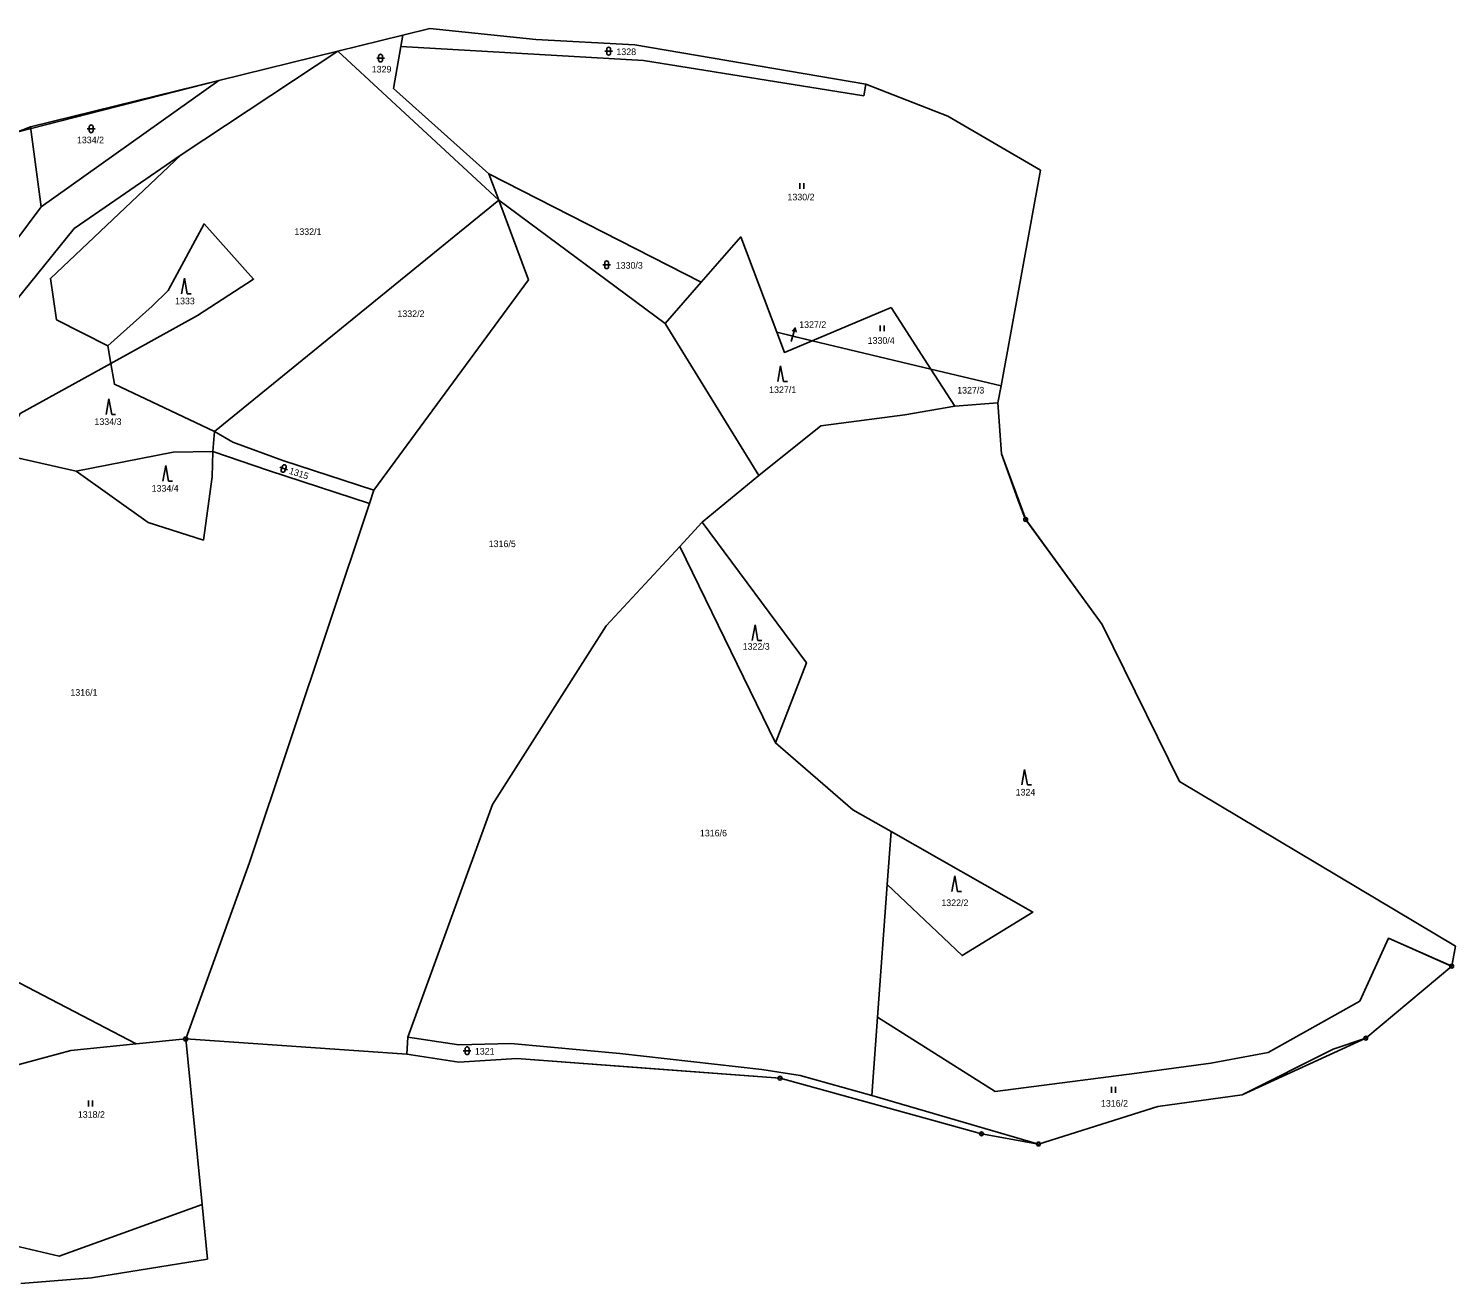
# Model space of a CAD drawing. Extents: x -760642 to -757221, y -1092371 to -1088855.
# Drawn here: x -758208 to -757841.3, y -1091740.5 to -1091418.1 of the extents above; entities that cross this region are included whole.
import ezdxf

# ---------------------------------------------------------------- set-up
doc = ezdxf.new("R2010")
doc.units = 0
for name, color, linetype in [('Vrstva 1', 7, 'Continuous'), ('Vrstva 13', 7, 'Continuous'), ('Vrstva 16', 7, 'Continuous'), ('Vrstva 18', 7, 'Continuous'), ('Vrstva 24', 7, 'Continuous'), ('Vrstva 25', 7, 'Continuous'), ('Vrstva 28', 7, 'Continuous'), ('Vrstva 30', 7, 'Continuous')]:
    doc.layers.add(name, color=color, linetype=linetype)

msp = doc.modelspace()

# ---------------------------------------------------------------- linework, layer by layer
at = {"layer": 'Vrstva 1'}
for p, q in [((-758112.36, -1091422.75), (-758111.85, -1091419.86)), ((-758168.83, -1091450.63), (-758128.51, -1091423.96)), ((-758128.51, -1091423.96), (-758087.19, -1091462.22)), ((-758114.26, -1091433.58), (-758112.36, -1091422.75)), ((-758112.36, -1091422.75), (-758049.99, -1091426.37)), ((-758049.99, -1091426.37), (-757993.39, -1091435.44)), ((-758204.82, -1091463.99), (-758159.15, -1091431.49)), ((-757993.39, -1091435.44), (-757992.81, -1091432.47)), ((-758114.26, -1091433.58), (-758089.71, -1091455.48)), ((-758207.52, -1091443.37), (-758204.82, -1091463.99)), ((-758202.42, -1091482.36), (-758168.83, -1091450.63)), ((-758196.3, -1091469.53), (-758168.83, -1091450.63)), ((-758089.71, -1091455.48), (-758035.17, -1091483.32)), ((-758089.71, -1091455.48), (-758087.19, -1091462.22)), ((-758087.19, -1091462.22), (-758160.27, -1091521.64)), ((-758087.19, -1091462.22), (-758044.43, -1091493.9)), ((-758087.19, -1091462.22), (-758079.54, -1091482.73)), ((-758211.58, -1091473.01), (-758204.82, -1091463.99)), ((-758196.3, -1091469.53), (-758215.33, -1091493.07)), ((-758172.17, -1091485.42), (-758162.91, -1091468.32)), ((-758162.91, -1091468.32), (-758150.19, -1091482.53)), ((-758024.99, -1091471.68), (-758035.17, -1091483.32)), ((-758015.74, -1091496.19), (-758024.99, -1091471.68)), ((-758202.42, -1091482.36), (-758200.82, -1091492.96)), ((-758164.59, -1091491.89), (-758150.19, -1091482.53)), ((-758079.54, -1091482.73), (-758119.27, -1091536.7)), ((-758035.17, -1091483.32), (-758044.43, -1091493.9)), ((-758176.26, -1091489.43), (-758172.17, -1091485.42)), ((-758187.63, -1091499.68), (-758176.26, -1091489.43)), ((-758186.87, -1091504.19), (-758164.59, -1091491.89)), ((-758006.66, -1091498.35), (-757986.38, -1091489.82)), ((-757986.38, -1091489.82), (-757976.11, -1091505.63)), ((-758200.82, -1091492.96), (-758187.63, -1091499.68)), ((-758044.43, -1091493.9), (-758020.39, -1091532.94)), ((-758015.74, -1091496.19), (-758006.66, -1091498.35)), ((-758015.74, -1091496.19), (-758013.79, -1091501.35)), ((-758013.79, -1091501.35), (-758006.66, -1091498.35)), ((-758006.66, -1091498.35), (-757976.11, -1091505.63)), ((-758186.87, -1091504.19), (-758187.63, -1091499.68)), ((-758210.23, -1091517.07), (-758186.87, -1091504.19)), ((-758185.98, -1091509.54), (-758186.87, -1091504.19)), ((-757976.11, -1091505.63), (-757969.99, -1091515.16)), ((-757976.11, -1091505.63), (-757958.1, -1091509.92)), ((-758185.98, -1091509.54), (-758160.27, -1091521.64)), ((-758004.45, -1091520.17), (-757982.84, -1091517.41)), ((-757982.84, -1091517.41), (-757969.99, -1091515.16)), ((-757969.99, -1091515.16), (-757958.91, -1091514.31)), ((-758004.45, -1091520.17), (-758020.39, -1091532.94)), ((-758160.27, -1091521.64), (-758160.66, -1091526.8)), ((-758160.27, -1091521.64), (-758155.56, -1091524.44)), ((-758155.56, -1091524.44), (-758142.67, -1091529.12)), ((-758215.93, -1091527.36), (-758195.84, -1091531.84)), ((-758170.85, -1091526.94), (-758195.84, -1091531.84)), ((-758170.85, -1091526.94), (-758160.66, -1091526.8)), ((-758160.66, -1091526.8), (-758160.85, -1091533.31)), ((-758160.66, -1091526.8), (-758146.35, -1091531.71)), ((-758177.34, -1091545.07), (-758195.84, -1091531.84)), ((-758146.35, -1091531.71), (-758120.38, -1091540.17)), ((-758142.67, -1091529.12), (-758119.27, -1091536.7)), ((-758160.85, -1091533.31), (-758163.08, -1091549.56)), ((-758020.39, -1091532.94), (-758034.93, -1091544.97)), ((-758120.38, -1091540.17), (-758119.27, -1091536.7)), ((-758120.38, -1091540.17), (-758151.24, -1091632.36)), ((-758177.34, -1091545.07), (-758163.08, -1091549.56)), ((-758034.93, -1091544.97), (-758040.69, -1091551.19)), ((-758034.93, -1091544.97), (-758008.13, -1091581.07)), ((-758040.69, -1091551.19), (-758059.6, -1091571.6)), ((-758016.08, -1091601.69), (-758040.69, -1091551.19)), ((-758059.6, -1091571.6), (-758088.81, -1091617.52)), ((-758008.13, -1091581.07), (-758016.08, -1091601.69)), ((-758016.08, -1091601.69), (-757996.2, -1091618.83)), ((-758088.81, -1091617.52), (-758110.52, -1091677.3)), ((-757996.2, -1091618.83), (-757986.31, -1091624.44)), ((-757986.31, -1091624.44), (-757987.33, -1091638.06)), ((-757986.31, -1091624.44), (-757949.89, -1091645.11)), ((-758151.24, -1091632.36), (-758167.65, -1091677.73)), ((-757987.33, -1091638.06), (-757989.87, -1091672.08)), ((-757968.11, -1091656.3), (-757987.33, -1091638.06)), ((-758246.49, -1091644.53), (-758180.41, -1091679.01)), ((-757949.89, -1091645.11), (-757968.11, -1091656.3)), ((-757865.85, -1091668), (-757858.55, -1091651.84)), ((-757858.55, -1091651.84), (-757842.28, -1091659.03)), ((-757889.42, -1091681.16), (-757865.85, -1091668)), ((-757989.87, -1091672.08), (-757991.33, -1091692.26)), ((-757989.87, -1091672.08), (-757959.6, -1091691.26)), ((-758167.65, -1091677.73), (-758180.41, -1091679.01)), ((-758110.52, -1091677.3), (-758110.78, -1091681.67)), ((-758110.52, -1091677.3), (-758097.42, -1091679.19)), ((-758097.42, -1091679.19), (-758084.11, -1091678.93)), ((-758084.11, -1091678.93), (-758056.08, -1091681.47)), ((-758197.14, -1091680.68), (-758234.93, -1091690.88)), ((-758180.41, -1091679.01), (-758197.14, -1091680.68)), ((-758056.08, -1091681.47), (-758019.55, -1091685.55)), ((-757904.14, -1091683.97), (-757889.42, -1091681.16)), ((-758019.55, -1091685.55), (-758009.76, -1091687.13)), ((-757923.24, -1091686.53), (-757904.14, -1091683.97)), ((-758009.76, -1091687.13), (-757991.33, -1091692.26)), ((-757959.6, -1091691.26), (-757923.24, -1091686.53)), ((-757991.33, -1091692.26), (-757948.47, -1091704.71)), ((-758200.18, -1091733.5), (-758163.46, -1091720.21)), ((-758221.61, -1091728.5), (-758200.18, -1091733.5))]:
    msp.add_line(p, q, dxfattribs=at)
at = {"layer": 'Vrstva 13'}
for p, q in [((-758111.85, -1091419.86), (-758104.89, -1091418.15)), ((-758104.89, -1091418.15), (-758077.63, -1091420.92)), ((-758128.51, -1091423.96), (-758111.85, -1091419.86)), ((-758077.63, -1091420.92), (-758052.21, -1091422.34)), ((-758159.15, -1091431.49), (-758128.51, -1091423.96)), ((-758052.21, -1091422.34), (-757992.81, -1091432.47)), ((-758207.52, -1091443.37), (-758159.15, -1091431.49)), ((-757992.81, -1091432.47), (-757971.76, -1091440.66)), ((-758207.52, -1091443.37), (-758211.02, -1091444.76)), ((-757971.76, -1091440.66), (-757947.92, -1091454.57)), ((-757958.1, -1091509.92), (-757947.92, -1091454.57)), ((-757958.91, -1091514.31), (-757958.1, -1091509.92)), ((-757958.91, -1091514.31), (-757958.02, -1091527.39)), ((-757958.02, -1091527.39), (-757953.68, -1091539.42)), ((-757953.68, -1091539.42), (-757951.77, -1091544.28)), ((-757951.77, -1091544.28), (-757932.12, -1091571.24)), ((-757932.12, -1091571.24), (-757912.21, -1091611.59)), ((-757912.21, -1091611.59), (-757841.31, -1091653.87)), ((-757841.31, -1091653.87), (-757842.28, -1091659.03)), ((-757842.28, -1091659.03), (-757864.35, -1091677.52)), ((-758163.46, -1091720.21), (-758167.65, -1091677.73)), ((-758110.78, -1091681.67), (-758167.65, -1091677.73)), ((-757864.35, -1091677.52), (-757872.73, -1091680.38)), ((-758097.45, -1091683.71), (-758110.78, -1091681.67)), ((-757872.73, -1091680.38), (-757896.17, -1091692.09)), ((-758082.57, -1091682.71), (-758097.45, -1091683.71)), ((-758046.15, -1091685.44), (-758082.57, -1091682.71)), ((-758014.9, -1091687.79), (-758046.15, -1091685.44)), ((-757975.44, -1091698.69), (-758014.9, -1091687.79)), ((-757896.17, -1091692.09), (-757917.77, -1091695.05)), ((-757917.77, -1091695.05), (-757948.47, -1091704.71)), ((-757963.11, -1091702.09), (-757975.44, -1091698.69)), ((-757948.47, -1091704.71), (-757963.11, -1091702.09)), ((-758162.07, -1091734.29), (-758163.46, -1091720.21)), ((-758162.07, -1091734.29), (-758191.83, -1091739.12)), ((-758191.83, -1091739.12), (-758210.04, -1091740.53))]:
    msp.add_line(p, q, dxfattribs=at)
at = {"layer": 'Vrstva 16'}
for p, q in [((-758011.84, -1091497.93), (-758010.974, -1091495.058)), ((-758012.01, -1091498.51), (-758011.84, -1091497.93))]:
    msp.add_line(p, q, dxfattribs=at)
msp.add_lwpolyline([(-758011.741, -1091495.871), (-758010.974, -1091495.058), (-758010.784, -1091496.159)], dxfattribs=at)
at = {"layer": 'Vrstva 24'}
for centre, radius in [((-757951.77, -1091544.28), 0.5), ((-757951.77, -1091544.28), 0.0327), ((-757842.28, -1091659.03), 0.5), ((-757842.28, -1091659.03), 0.0327), ((-758167.65, -1091677.73), 0.5), ((-758167.65, -1091677.73), 0.0327), ((-757864.35, -1091677.52), 0.5), ((-757864.35, -1091677.52), 0.0327), ((-758014.9, -1091687.79), 0.5), ((-758014.9, -1091687.79), 0.0327), ((-757963.11, -1091702.09), 0.5), ((-757963.11, -1091702.09), 0.0327), ((-757948.47, -1091704.71), 0.5), ((-757948.47, -1091704.71), 0.0327)]:
    msp.add_circle(centre, radius, dxfattribs=at)
at = {"layer": 'Vrstva 25'}
for p, q in [((-758118.57, -1091425.74), (-758116.57, -1091425.74)), ((-758118.07, -1091426.24), (-758118.07, -1091425.24)), ((-758117.07, -1091426.24), (-758117.07, -1091425.24)), ((-758059.95, -1091423.97), (-758057.95, -1091423.97)), ((-758059.45, -1091424.47), (-758059.45, -1091423.47)), ((-758058.45, -1091424.47), (-758058.45, -1091423.47)), ((-758192.95, -1091443.91), (-758190.95, -1091443.91)), ((-758192.45, -1091444.41), (-758192.45, -1091443.41)), ((-758191.45, -1091444.41), (-758191.45, -1091443.41)), ((-758009.837, -1091457.855), (-758009.837, -1091459.355)), ((-758008.815, -1091459.355), (-758008.815, -1091457.855)), ((-758060.46, -1091478.83), (-758058.46, -1091478.83)), ((-758059.96, -1091479.33), (-758059.96, -1091478.33)), ((-758058.96, -1091479.33), (-758058.96, -1091478.33)), ((-758167.972, -1091482.279), (-758168.705, -1091486.279)), ((-758167.972, -1091482.279), (-758167.239, -1091486.279)), ((-758167.239, -1091486.279), (-758166.239, -1091486.279)), ((-757989.147, -1091494.415), (-757989.147, -1091495.915)), ((-757988.125, -1091495.915), (-757988.125, -1091494.415)), ((-758014.742, -1091504.779), (-758015.475, -1091508.779)), ((-758014.742, -1091504.779), (-758014.009, -1091508.779)), ((-758014.009, -1091508.779), (-758013.009, -1091508.779)), ((-758187.402, -1091513.279), (-758188.135, -1091517.279)), ((-758187.402, -1091513.279), (-758186.669, -1091517.279)), ((-758186.669, -1091517.279), (-758185.669, -1091517.279)), ((-758172.792, -1091530.409), (-758173.525, -1091534.409)), ((-758172.792, -1091530.409), (-758172.059, -1091534.409)), ((-758143.416, -1091530.872), (-758141.512, -1091531.484)), ((-758143.093, -1091531.501), (-758142.787, -1091530.549)), ((-758142.141, -1091531.807), (-758141.835, -1091530.855)), ((-758172.059, -1091534.409), (-758171.059, -1091534.409)), ((-758021.302, -1091571.329), (-758022.035, -1091575.329)), ((-758021.302, -1091571.329), (-758020.569, -1091575.329)), ((-758020.569, -1091575.329), (-758019.569, -1091575.329)), ((-757952.042, -1091608.469), (-757952.775, -1091612.469)), ((-757952.042, -1091608.469), (-757951.309, -1091612.469)), ((-757951.309, -1091612.469), (-757950.309, -1091612.469)), ((-757970.012, -1091635.849), (-757970.745, -1091639.849)), ((-757970.012, -1091635.849), (-757969.279, -1091639.849)), ((-757969.279, -1091639.849), (-757968.279, -1091639.849)), ((-758096.33, -1091680.74), (-758094.33, -1091680.74)), ((-758095.83, -1091681.24), (-758095.83, -1091680.24)), ((-758094.83, -1091681.24), (-758094.83, -1091680.24)), ((-758192.597, -1091693.545), (-758192.597, -1091695.045)), ((-758191.575, -1091695.045), (-758191.575, -1091693.545)), ((-757929.677, -1091690.055), (-757929.677, -1091691.555)), ((-757928.655, -1091691.555), (-757928.655, -1091690.055))]:
    msp.add_line(p, q, dxfattribs=at)
for centre, start, end in [((-758117.57, -1091425.24), 0, 180), ((-758058.95, -1091423.47), 0, 180), ((-758058.95, -1091424.47), 180, 0), ((-758117.57, -1091426.24), 180, 0), ((-758191.95, -1091443.41), 0, 180), ((-758191.95, -1091444.41), 180, 0), ((-758059.46, -1091478.33), 0, 180), ((-758059.46, -1091479.33), 180, 0), ((-758142.617, -1091531.654), 162.17298, 342.17298), ((-758142.311, -1091530.702), 342.17298, 162.17298), ((-758095.33, -1091680.24), 0, 180), ((-758095.33, -1091681.24), 180, 0)]:
    msp.add_arc(centre, 0.5, start, end, dxfattribs=at)
at = {"layer": 'Vrstva 28'}
msp.add_lwpolyline([(-758211.02, -1091444.76), (-758159.15, -1091431.49), (-758128.51, -1091423.96), (-758111.85, -1091419.86), (-758104.89, -1091418.15), (-758077.63, -1091420.92), (-758052.21, -1091422.34), (-757992.81, -1091432.47), (-757971.76, -1091440.66), (-757947.92, -1091454.57), (-757958.1, -1091509.92), (-757958.91, -1091514.31), (-757958.02, -1091527.39), (-757951.77, -1091544.28), (-757932.12, -1091571.24), (-757912.21, -1091611.59), (-757841.31, -1091653.87), (-757842.28, -1091659.03), (-757864.35, -1091677.52), (-757896.17, -1091692.09), (-757917.77, -1091695.05), (-757948.47, -1091704.71), (-757963.11, -1091702.09), (-757975.44, -1091698.69), (-758014.9, -1091687.79), (-758082.57, -1091682.71), (-758097.45, -1091683.71), (-758110.78, -1091681.67), (-758167.65, -1091677.73), (-758163.46, -1091720.21), (-758162.07, -1091734.29), (-758191.83, -1091739.12), (-758210.04, -1091740.53)], dxfattribs=at)
at = {"layer": 'Vrstva 30'}
for points in [[(-758176.26, -1091489.43), (-758172.17, -1091485.42), (-758162.91, -1091468.32), (-758150.19, -1091482.53), (-758164.59, -1091491.89), (-758186.87, -1091504.19), (-758185.98, -1091509.54), (-758160.27, -1091521.64), (-758087.19, -1091462.22), (-758128.51, -1091423.96), (-758168.83, -1091450.63), (-758202.42, -1091482.36), (-758200.82, -1091492.96), (-758187.63, -1091499.68), (-758176.26, -1091489.43)], [(-758187.63, -1091499.68), (-758200.82, -1091492.96), (-758202.42, -1091482.36), (-758168.83, -1091450.63), (-758196.3, -1091469.53), (-758215.33, -1091493.07), (-758243.33, -1091526.1), (-758304.48, -1091535.49), (-758320.25, -1091545.14), (-758296.34, -1091537.91), (-758215.93, -1091527.36), (-758210.23, -1091517.07), (-758186.87, -1091504.19), (-758187.63, -1091499.68)], [(-758176.26, -1091489.43), (-758187.63, -1091499.68), (-758186.87, -1091504.19), (-758164.59, -1091491.89), (-758150.19, -1091482.53), (-758162.91, -1091468.32), (-758172.17, -1091485.42), (-758176.26, -1091489.43)], [(-757969.99, -1091515.16), (-757976.11, -1091505.63), (-758006.66, -1091498.35), (-758013.79, -1091501.35), (-758015.74, -1091496.19), (-758024.99, -1091471.68), (-758035.17, -1091483.32), (-758044.43, -1091493.9), (-758020.39, -1091532.94), (-758004.45, -1091520.17), (-757982.84, -1091517.41), (-757969.99, -1091515.16)], [(-758011.611, -1091497.172), (-758015.74, -1091496.19), (-758013.79, -1091501.35), (-758006.66, -1091498.35), (-758011.611, -1091497.172)], [(-758185.98, -1091509.54), (-758186.87, -1091504.19), (-758210.23, -1091517.07), (-758215.93, -1091527.36), (-758195.84, -1091531.84), (-758170.85, -1091526.94), (-758160.66, -1091526.8), (-758160.27, -1091521.64), (-758185.98, -1091509.54)], [(-757958.91, -1091514.31), (-757958.1, -1091509.92), (-757976.11, -1091505.63), (-757969.99, -1091515.16), (-757958.91, -1091514.31)], [(-757951.953, -1091543.815), (-757953.68, -1091539.42), (-757958.02, -1091527.39), (-757958.91, -1091514.31), (-757969.99, -1091515.16), (-757982.84, -1091517.41), (-758004.45, -1091520.17), (-758020.39, -1091532.94), (-758034.93, -1091544.97), (-758008.13, -1091581.07), (-758016.08, -1091601.69), (-757996.2, -1091618.83), (-757986.31, -1091624.44), (-757949.89, -1091645.11), (-757968.11, -1091656.3), (-757987.33, -1091638.06), (-757989.87, -1091672.08), (-757959.6, -1091691.26), (-757923.24, -1091686.53), (-757904.14, -1091683.97), (-757889.42, -1091681.16), (-757865.85, -1091668), (-757858.55, -1091651.84), (-757842.737, -1091658.828)], [(-758160.66, -1091526.8), (-758170.85, -1091526.94), (-758195.84, -1091531.84), (-758177.34, -1091545.07), (-758163.08, -1091549.56), (-758160.85, -1091533.31), (-758160.66, -1091526.8)], [(-758040.69, -1091551.19), (-758016.08, -1091601.69), (-758008.13, -1091581.07), (-758034.93, -1091544.97), (-758040.69, -1091551.19)], [(-757842.188, -1091658.539), (-757841.31, -1091653.87), (-757912.21, -1091611.59), (-757932.12, -1091571.24), (-757951.475, -1091544.684)], [(-757986.31, -1091624.44), (-757987.33, -1091638.06), (-757968.11, -1091656.3), (-757949.89, -1091645.11), (-757986.31, -1091624.44)]]:
    msp.add_lwpolyline(points, dxfattribs=at)
for centre, start, end in [((-757951.77, -1091544.28), 111.45503, 180), ((-757951.77, -1091544.28), 180, 306.08672), ((-757842.28, -1091659.03), 79.35353, 156.15852)]:
    msp.add_arc(centre, 0.5, start, end, dxfattribs=at)

# ---------------------------------------------------------------- texts
at = {"layer": 'Vrstva 16'}
msp.add_text('1327/2', height=1.7, dxfattribs=at).set_placement((-758009.97, -1091495.06))
at = {"layer": 'Vrstva 18'}
for s, height, p in [('1328', 1.7, (-758056.954, -1091424.97)), ('1329', 1.7, (-758119.84, -1091429.44)), ('1334/2', 1.7, (-758195.6, -1091447.61)), ('1330/2', 1.7, (-758012.99, -1091462.29)), ('1332/1', 1.7, (-758139.71, -1091471.17)), ('1330/3', 1.7, (-758057.13, -1091479.84)), ('1333', 1.7, (-758170.37, -1091488.99)), ('1332/2', 1.7, (-758113.24, -1091492.27)), ('1327/2', 0.1, (-758012.173, -1091498.51)), ('1330/4', 1.7, (-757992.38, -1091499.15)), ('1327/1', 1.7, (-758017.7, -1091511.79)), ('1327/3', 1.7, (-757969.37, -1091511.91)), ('1334/3', 1.7, (-758191.1, -1091519.99)), ('1334/4', 1.7, (-758176.41, -1091537.12)), ('1316/5', 1.7, (-758089.77, -1091551.37)), ('1322/3', 1.7, (-758024.51, -1091577.74)), ('1316/1', 1.7, (-758197.28, -1091589.55)), ('1324', 1.7, (-757954.35, -1091615.18)), ('1316/6', 1.7, (-758035.49, -1091625.69)), ('1322/2', 1.7, (-757973.44, -1091643.59)), ('1321', 1.7, (-758093.33, -1091681.74)), ('1316/2', 1.7, (-757932.42, -1091695.11)), ('1318/2', 1.7, (-758195.37, -1091697.98))]:
    msp.add_text(s, height=height, dxfattribs=at).set_placement(p)
msp.add_text('1315', height=1.7, rotation=342.17298, dxfattribs=at).set_placement((-758141.23, -1091532.49))

doc.saveas('drawing.dxf')
